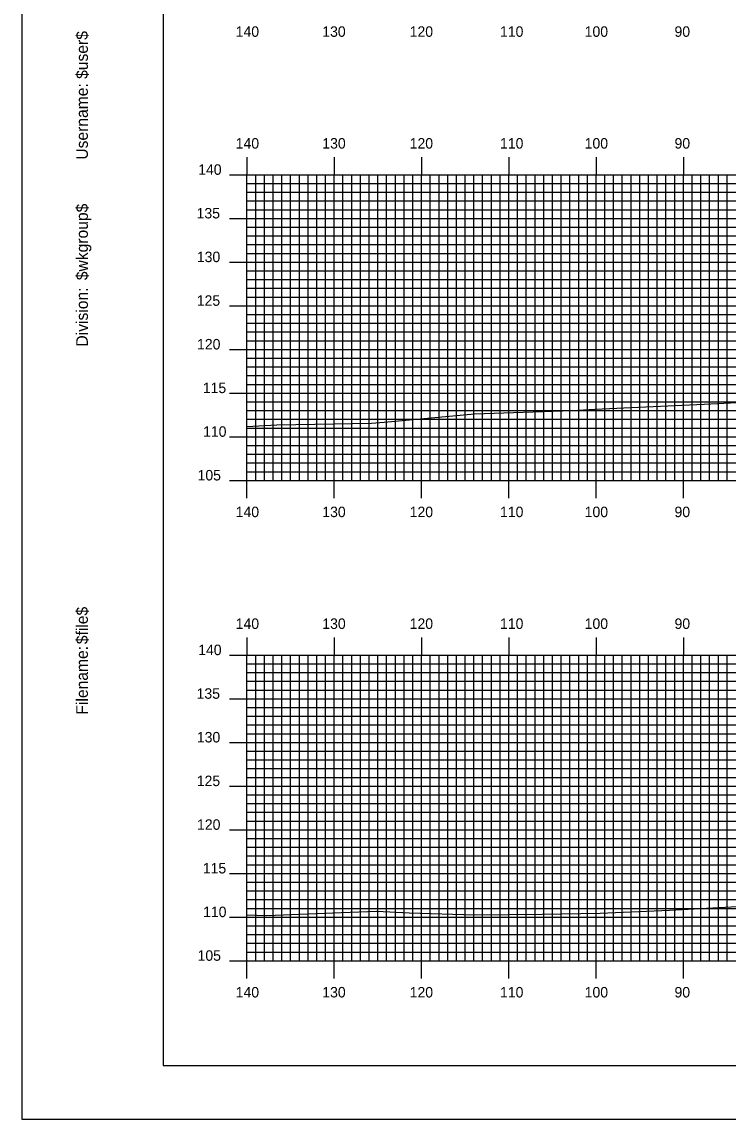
# Model space of a CAD drawing. Extents: x 1782254 to 1782597, y 442591 to 442811.
# Drawn here: x 1782253.6 to 1782334.5, y 442590.5 to 442716.2 of the extents above; entities that cross this region are included whole.
import ezdxf

# ---------------------------------------------------------------- set-up
doc = ezdxf.new("R2010")
doc.units = 0
for name, color, linetype in [('BORDER', 7, 'Continuous'), ('H_V ANNOTATION', 7, 'Continuous'), ('MAJOR', 7, 'Continuous'), ('MINOR', 7, 'Continuous'), ('PLOT BOUNDARY', 7, 'Continuous'), ('S_Roadway_Centerline', 7, 'Continuous')]:
    doc.layers.add(name, color=color, linetype=linetype)

msp = doc.modelspace()

# ---------------------------------------------------------------- linework, layer by layer
at = {"layer": 'BORDER'}
msp.add_lwpolyline([(1782269.83, 442596.67), (1782589.83, 442596.67), (1782589.83, 442806.67), (1782269.83, 442806.67)], close=True, dxfattribs=at)
at = {"layer": 'MAJOR'}
for p, q in [((1782279.43, 442700.67), (1782279.43, 442698.67)), ((1782289.43, 442700.67), (1782289.43, 442698.67)), ((1782299.43, 442700.67), (1782299.43, 442698.67)), ((1782309.43, 442700.67), (1782309.43, 442698.67)), ((1782319.43, 442700.67), (1782319.43, 442698.67)), ((1782329.43, 442700.67), (1782329.43, 442698.67)), ((1782277.43, 442698.67), (1782279.43, 442698.67)), ((1782279.43, 442698.67), (1782559.43, 442698.67)), ((1782279.43, 442663.67), (1782279.43, 442698.67)), ((1782279.43, 442663.67), (1782279.43, 442698.67)), ((1782279.43, 442698.67), (1782559.43, 442698.67)), ((1782289.43, 442663.67), (1782289.43, 442698.67)), ((1782299.43, 442663.67), (1782299.43, 442698.67)), ((1782309.43, 442663.67), (1782309.43, 442698.67)), ((1782319.43, 442663.67), (1782319.43, 442698.67)), ((1782329.43, 442663.67), (1782329.43, 442698.67)), ((1782277.43, 442693.67), (1782279.43, 442693.67)), ((1782279.43, 442693.67), (1782559.43, 442693.67)), ((1782277.43, 442688.67), (1782279.43, 442688.67)), ((1782279.43, 442688.67), (1782559.43, 442688.67)), ((1782277.43, 442683.67), (1782279.43, 442683.67)), ((1782279.43, 442683.67), (1782559.43, 442683.67)), ((1782277.43, 442678.67), (1782279.43, 442678.67)), ((1782279.43, 442678.67), (1782559.43, 442678.67)), ((1782277.43, 442673.67), (1782279.43, 442673.67)), ((1782279.43, 442673.67), (1782559.43, 442673.67)), ((1782277.43, 442668.67), (1782279.43, 442668.67)), ((1782279.43, 442668.67), (1782559.43, 442668.67)), ((1782277.43, 442663.67), (1782279.43, 442663.67)), ((1782279.43, 442663.67), (1782559.43, 442663.67)), ((1782279.43, 442663.67), (1782559.43, 442663.67)), ((1782279.43, 442661.66), (1782279.43, 442663.67)), ((1782289.43, 442661.66), (1782289.43, 442663.67)), ((1782299.43, 442661.66), (1782299.43, 442663.67)), ((1782309.43, 442661.66), (1782309.43, 442663.67)), ((1782319.43, 442661.66), (1782319.43, 442663.67)), ((1782329.43, 442661.66), (1782329.43, 442663.67)), ((1782279.43, 442645.67), (1782279.43, 442643.67)), ((1782289.43, 442645.67), (1782289.43, 442643.67)), ((1782299.43, 442645.67), (1782299.43, 442643.67)), ((1782309.43, 442645.67), (1782309.43, 442643.67)), ((1782319.43, 442645.67), (1782319.43, 442643.67)), ((1782329.43, 442645.67), (1782329.43, 442643.67)), ((1782277.43, 442643.67), (1782279.43, 442643.67)), ((1782279.43, 442643.67), (1782559.43, 442643.67)), ((1782279.43, 442608.67), (1782279.43, 442643.67)), ((1782279.43, 442608.67), (1782279.43, 442643.67)), ((1782279.43, 442643.67), (1782559.43, 442643.67)), ((1782289.43, 442608.67), (1782289.43, 442643.67)), ((1782299.43, 442608.67), (1782299.43, 442643.67)), ((1782309.43, 442608.67), (1782309.43, 442643.67)), ((1782319.43, 442608.67), (1782319.43, 442643.67)), ((1782329.43, 442608.67), (1782329.43, 442643.67)), ((1782277.43, 442638.67), (1782279.43, 442638.67)), ((1782279.43, 442638.67), (1782559.43, 442638.67)), ((1782277.43, 442633.67), (1782279.43, 442633.67)), ((1782279.43, 442633.67), (1782559.43, 442633.67)), ((1782277.43, 442628.67), (1782279.43, 442628.67)), ((1782279.43, 442628.67), (1782559.43, 442628.67)), ((1782277.43, 442623.67), (1782279.43, 442623.67)), ((1782279.43, 442623.67), (1782559.43, 442623.67)), ((1782277.43, 442618.67), (1782279.43, 442618.67)), ((1782279.43, 442618.67), (1782559.43, 442618.67)), ((1782277.43, 442613.67), (1782279.43, 442613.67)), ((1782279.43, 442613.67), (1782559.43, 442613.67)), ((1782277.43, 442608.67), (1782279.43, 442608.67)), ((1782279.43, 442608.67), (1782559.43, 442608.67)), ((1782279.43, 442608.67), (1782559.43, 442608.67)), ((1782279.43, 442606.66), (1782279.43, 442608.67)), ((1782289.43, 442606.66), (1782289.43, 442608.67)), ((1782299.43, 442606.66), (1782299.43, 442608.67)), ((1782309.43, 442606.66), (1782309.43, 442608.67)), ((1782319.43, 442606.66), (1782319.43, 442608.67)), ((1782329.43, 442606.66), (1782329.43, 442608.67))]:
    msp.add_line(p, q, dxfattribs=at)
at = {"layer": 'MINOR'}
for p, q in [((1782280.43, 442663.67), (1782280.43, 442698.67)), ((1782281.43, 442663.67), (1782281.43, 442698.67)), ((1782282.43, 442663.67), (1782282.43, 442698.67)), ((1782283.43, 442663.67), (1782283.43, 442698.67)), ((1782284.43, 442663.67), (1782284.43, 442698.67)), ((1782285.43, 442663.67), (1782285.43, 442698.67)), ((1782286.43, 442663.67), (1782286.43, 442698.67)), ((1782287.43, 442663.67), (1782287.43, 442698.67)), ((1782288.43, 442663.67), (1782288.43, 442698.67)), ((1782290.43, 442663.67), (1782290.43, 442698.67)), ((1782291.43, 442663.67), (1782291.43, 442698.67)), ((1782292.43, 442663.67), (1782292.43, 442698.67)), ((1782293.43, 442663.67), (1782293.43, 442698.67)), ((1782294.43, 442663.67), (1782294.43, 442698.67)), ((1782295.43, 442663.67), (1782295.43, 442698.67)), ((1782296.43, 442663.67), (1782296.43, 442698.67)), ((1782297.43, 442663.67), (1782297.43, 442698.67)), ((1782298.43, 442663.67), (1782298.43, 442698.67)), ((1782300.43, 442663.67), (1782300.43, 442698.67)), ((1782301.43, 442663.67), (1782301.43, 442698.67)), ((1782302.43, 442663.67), (1782302.43, 442698.67)), ((1782303.43, 442663.67), (1782303.43, 442698.67)), ((1782304.43, 442663.67), (1782304.43, 442698.67)), ((1782305.43, 442663.67), (1782305.43, 442698.67)), ((1782306.43, 442663.67), (1782306.43, 442698.67)), ((1782307.43, 442663.67), (1782307.43, 442698.67)), ((1782308.43, 442663.67), (1782308.43, 442698.67)), ((1782310.43, 442663.67), (1782310.43, 442698.67)), ((1782311.43, 442663.67), (1782311.43, 442698.67)), ((1782312.43, 442663.67), (1782312.43, 442698.67)), ((1782313.43, 442663.67), (1782313.43, 442698.67)), ((1782314.43, 442663.67), (1782314.43, 442698.67)), ((1782315.43, 442663.67), (1782315.43, 442698.67)), ((1782316.43, 442663.67), (1782316.43, 442698.67)), ((1782317.43, 442663.67), (1782317.43, 442698.67)), ((1782318.43, 442663.67), (1782318.43, 442698.67)), ((1782320.43, 442663.67), (1782320.43, 442698.67)), ((1782321.43, 442663.67), (1782321.43, 442698.67)), ((1782322.43, 442663.67), (1782322.43, 442698.67)), ((1782323.43, 442663.67), (1782323.43, 442698.67)), ((1782324.43, 442663.67), (1782324.43, 442698.67)), ((1782325.43, 442663.67), (1782325.43, 442698.67)), ((1782326.43, 442663.67), (1782326.43, 442698.67)), ((1782327.43, 442663.67), (1782327.43, 442698.67)), ((1782328.43, 442663.67), (1782328.43, 442698.67)), ((1782330.43, 442663.67), (1782330.43, 442698.67)), ((1782331.43, 442663.67), (1782331.43, 442698.67)), ((1782332.43, 442663.67), (1782332.43, 442698.67)), ((1782333.43, 442663.67), (1782333.43, 442698.67)), ((1782334.43, 442663.67), (1782334.43, 442698.67)), ((1782279.43, 442697.67), (1782559.43, 442697.67)), ((1782279.43, 442697.67), (1782281.44, 442697.67)), ((1782279.43, 442696.67), (1782559.43, 442696.67)), ((1782279.43, 442696.67), (1782281.44, 442696.67)), ((1782279.43, 442695.67), (1782559.43, 442695.67)), ((1782279.43, 442695.67), (1782281.44, 442695.67)), ((1782279.43, 442694.67), (1782559.43, 442694.67)), ((1782279.43, 442694.67), (1782281.44, 442694.67)), ((1782279.43, 442692.67), (1782559.43, 442692.67)), ((1782279.43, 442692.67), (1782281.44, 442692.67)), ((1782279.43, 442691.67), (1782559.43, 442691.67)), ((1782279.43, 442691.67), (1782281.44, 442691.67)), ((1782279.43, 442690.67), (1782559.43, 442690.67)), ((1782279.43, 442690.67), (1782281.44, 442690.67)), ((1782279.43, 442689.67), (1782559.43, 442689.67)), ((1782279.43, 442689.67), (1782281.44, 442689.67)), ((1782279.43, 442687.67), (1782559.43, 442687.67)), ((1782279.43, 442687.67), (1782281.44, 442687.67)), ((1782279.43, 442686.67), (1782559.43, 442686.67)), ((1782279.43, 442686.67), (1782281.44, 442686.67)), ((1782279.43, 442685.67), (1782559.43, 442685.67)), ((1782279.43, 442685.67), (1782281.44, 442685.67)), ((1782279.43, 442684.67), (1782559.43, 442684.67)), ((1782279.43, 442684.67), (1782281.44, 442684.67)), ((1782279.43, 442682.67), (1782559.43, 442682.67)), ((1782279.43, 442682.67), (1782281.44, 442682.67)), ((1782279.43, 442681.67), (1782559.43, 442681.67)), ((1782279.43, 442681.67), (1782281.44, 442681.67)), ((1782279.43, 442680.67), (1782559.43, 442680.67)), ((1782279.43, 442680.67), (1782281.44, 442680.67)), ((1782279.43, 442679.67), (1782559.43, 442679.67)), ((1782279.43, 442679.67), (1782281.44, 442679.67)), ((1782279.43, 442677.67), (1782559.43, 442677.67)), ((1782279.43, 442677.67), (1782281.44, 442677.67)), ((1782279.43, 442676.67), (1782559.43, 442676.67)), ((1782279.43, 442676.67), (1782281.44, 442676.67)), ((1782279.43, 442675.67), (1782559.43, 442675.67)), ((1782279.43, 442675.67), (1782281.44, 442675.67)), ((1782279.43, 442674.67), (1782559.43, 442674.67)), ((1782279.43, 442674.67), (1782281.44, 442674.67)), ((1782279.43, 442672.67), (1782559.43, 442672.67)), ((1782279.43, 442672.67), (1782281.44, 442672.67)), ((1782279.43, 442671.67), (1782559.43, 442671.67)), ((1782279.43, 442671.67), (1782281.44, 442671.67)), ((1782279.43, 442670.67), (1782559.43, 442670.67)), ((1782279.43, 442670.67), (1782281.44, 442670.67)), ((1782279.43, 442669.67), (1782559.43, 442669.67)), ((1782279.43, 442669.67), (1782281.44, 442669.67)), ((1782279.43, 442667.67), (1782559.43, 442667.67)), ((1782279.43, 442667.67), (1782281.44, 442667.67)), ((1782279.43, 442666.67), (1782559.43, 442666.67)), ((1782279.43, 442666.67), (1782281.44, 442666.67)), ((1782279.43, 442665.67), (1782559.43, 442665.67)), ((1782279.43, 442665.67), (1782281.44, 442665.67)), ((1782279.43, 442664.67), (1782559.43, 442664.67)), ((1782279.43, 442664.67), (1782281.44, 442664.67)), ((1782280.43, 442608.67), (1782280.43, 442643.67)), ((1782281.43, 442608.67), (1782281.43, 442643.67)), ((1782282.43, 442608.67), (1782282.43, 442643.67)), ((1782283.43, 442608.67), (1782283.43, 442643.67)), ((1782284.43, 442608.67), (1782284.43, 442643.67)), ((1782285.43, 442608.67), (1782285.43, 442643.67)), ((1782286.43, 442608.67), (1782286.43, 442643.67)), ((1782287.43, 442608.67), (1782287.43, 442643.67)), ((1782288.43, 442608.67), (1782288.43, 442643.67)), ((1782290.43, 442608.67), (1782290.43, 442643.67)), ((1782291.43, 442608.67), (1782291.43, 442643.67)), ((1782292.43, 442608.67), (1782292.43, 442643.67)), ((1782293.43, 442608.67), (1782293.43, 442643.67)), ((1782294.43, 442608.67), (1782294.43, 442643.67)), ((1782295.43, 442608.67), (1782295.43, 442643.67)), ((1782296.43, 442608.67), (1782296.43, 442643.67)), ((1782297.43, 442608.67), (1782297.43, 442643.67)), ((1782298.43, 442608.67), (1782298.43, 442643.67)), ((1782300.43, 442608.67), (1782300.43, 442643.67)), ((1782301.43, 442608.67), (1782301.43, 442643.67)), ((1782302.43, 442608.67), (1782302.43, 442643.67)), ((1782303.43, 442608.67), (1782303.43, 442643.67)), ((1782304.43, 442608.67), (1782304.43, 442643.67)), ((1782305.43, 442608.67), (1782305.43, 442643.67)), ((1782306.43, 442608.67), (1782306.43, 442643.67)), ((1782307.43, 442608.67), (1782307.43, 442643.67)), ((1782308.43, 442608.67), (1782308.43, 442643.67)), ((1782310.43, 442608.67), (1782310.43, 442643.67)), ((1782311.43, 442608.67), (1782311.43, 442643.67)), ((1782312.43, 442608.67), (1782312.43, 442643.67)), ((1782313.43, 442608.67), (1782313.43, 442643.67)), ((1782314.43, 442608.67), (1782314.43, 442643.67)), ((1782315.43, 442608.67), (1782315.43, 442643.67)), ((1782316.43, 442608.67), (1782316.43, 442643.67)), ((1782317.43, 442608.67), (1782317.43, 442643.67)), ((1782318.43, 442608.67), (1782318.43, 442643.67)), ((1782320.43, 442608.67), (1782320.43, 442643.67)), ((1782321.43, 442608.67), (1782321.43, 442643.67)), ((1782322.43, 442608.67), (1782322.43, 442643.67)), ((1782323.43, 442608.67), (1782323.43, 442643.67)), ((1782324.43, 442608.67), (1782324.43, 442643.67)), ((1782325.43, 442608.67), (1782325.43, 442643.67)), ((1782326.43, 442608.67), (1782326.43, 442643.67)), ((1782327.43, 442608.67), (1782327.43, 442643.67)), ((1782328.43, 442608.67), (1782328.43, 442643.67)), ((1782330.43, 442608.67), (1782330.43, 442643.67)), ((1782331.43, 442608.67), (1782331.43, 442643.67)), ((1782332.43, 442608.67), (1782332.43, 442643.67)), ((1782333.43, 442608.67), (1782333.43, 442643.67)), ((1782334.43, 442608.67), (1782334.43, 442643.67)), ((1782279.43, 442642.67), (1782559.43, 442642.67)), ((1782279.43, 442642.67), (1782281.44, 442642.67)), ((1782279.43, 442641.67), (1782559.43, 442641.67)), ((1782279.43, 442641.67), (1782281.44, 442641.67)), ((1782279.43, 442640.67), (1782559.43, 442640.67)), ((1782279.43, 442640.67), (1782281.44, 442640.67)), ((1782279.43, 442639.67), (1782559.43, 442639.67)), ((1782279.43, 442639.67), (1782281.44, 442639.67)), ((1782279.43, 442637.67), (1782559.43, 442637.67)), ((1782279.43, 442637.67), (1782281.44, 442637.67)), ((1782279.43, 442636.67), (1782559.43, 442636.67)), ((1782279.43, 442636.67), (1782281.44, 442636.67)), ((1782279.43, 442635.67), (1782559.43, 442635.67)), ((1782279.43, 442635.67), (1782281.44, 442635.67)), ((1782279.43, 442634.67), (1782559.43, 442634.67)), ((1782279.43, 442634.67), (1782281.44, 442634.67)), ((1782279.43, 442632.67), (1782559.43, 442632.67)), ((1782279.43, 442632.67), (1782281.44, 442632.67)), ((1782279.43, 442631.67), (1782559.43, 442631.67)), ((1782279.43, 442631.67), (1782281.44, 442631.67)), ((1782279.43, 442630.67), (1782559.43, 442630.67)), ((1782279.43, 442630.67), (1782281.44, 442630.67)), ((1782279.43, 442629.67), (1782559.43, 442629.67)), ((1782279.43, 442629.67), (1782281.44, 442629.67)), ((1782279.43, 442627.67), (1782559.43, 442627.67)), ((1782279.43, 442627.67), (1782281.44, 442627.67)), ((1782279.43, 442626.67), (1782559.43, 442626.67)), ((1782279.43, 442626.67), (1782281.44, 442626.67)), ((1782279.43, 442625.67), (1782559.43, 442625.67)), ((1782279.43, 442625.67), (1782281.44, 442625.67)), ((1782279.43, 442624.67), (1782559.43, 442624.67)), ((1782279.43, 442624.67), (1782281.44, 442624.67)), ((1782279.43, 442622.67), (1782559.43, 442622.67)), ((1782279.43, 442622.67), (1782281.44, 442622.67)), ((1782279.43, 442621.67), (1782559.43, 442621.67)), ((1782279.43, 442621.67), (1782281.44, 442621.67)), ((1782279.43, 442620.67), (1782559.43, 442620.67)), ((1782279.43, 442620.67), (1782281.44, 442620.67)), ((1782279.43, 442619.67), (1782559.43, 442619.67)), ((1782279.43, 442619.67), (1782281.44, 442619.67)), ((1782279.43, 442617.67), (1782559.43, 442617.67)), ((1782279.43, 442617.67), (1782281.44, 442617.67)), ((1782279.43, 442616.67), (1782559.43, 442616.67)), ((1782279.43, 442616.67), (1782281.44, 442616.67)), ((1782279.43, 442615.67), (1782559.43, 442615.67)), ((1782279.43, 442615.67), (1782281.44, 442615.67)), ((1782279.43, 442614.67), (1782559.43, 442614.67)), ((1782279.43, 442614.67), (1782281.44, 442614.67)), ((1782279.43, 442612.67), (1782559.43, 442612.67)), ((1782279.43, 442612.67), (1782281.44, 442612.67)), ((1782279.43, 442611.67), (1782559.43, 442611.67)), ((1782279.43, 442611.67), (1782281.44, 442611.67)), ((1782279.43, 442610.67), (1782559.43, 442610.67)), ((1782279.43, 442610.67), (1782281.44, 442610.67)), ((1782279.43, 442609.67), (1782559.43, 442609.67)), ((1782279.43, 442609.67), (1782281.44, 442609.67))]:
    msp.add_line(p, q, dxfattribs=at)
at = {"layer": 'PLOT BOUNDARY'}
msp.add_lwpolyline([(1782253.65, 442590.55), (1782593.65, 442590.55), (1782593.65, 442810.55), (1782253.65, 442810.55)], close=True, dxfattribs=at)
at = {"layer": 'S_Roadway_Centerline'}
for points in [[(1782279.43, 442669.86), (1782282.84, 442670.04), (1782293.7, 442670.23), (1782295.13, 442670.36), (1782305.51, 442671.3), (1782316.67, 442671.69), (1782319.27, 442671.85), (1782331.82, 442672.41), (1782339.36, 442672.79)], [(1782279.43, 442613.92), (1782281.69, 442613.84), (1782290.23, 442614.19), (1782294.3, 442614.37), (1782298, 442614.17), (1782305.54, 442613.92), (1782313.24, 442613.99), (1782319.9, 442614.13), (1782327.84, 442614.47), (1782337.05, 442614.95)]]:
    msp.add_lwpolyline(points, dxfattribs=at)

# ---------------------------------------------------------------- texts
at = {"layer": 'BORDER'}
for s, p in [('$user$', (1782261.2, 442709.65)), ('$user$', (1782261.2, 442709.65)), ('Username:', (1782261.2, 442700.4)), ('Username:', (1782261.2, 442700.4)), ('$wkgroup$', (1782261.2, 442686.6)), ('$wkgroup$', (1782261.2, 442686.6)), ('Division:', (1782261.2, 442679)), ('Division:', (1782261.2, 442679)), ('$file$', (1782261.2, 442644.92)), ('$file$', (1782261.2, 442644.92)), ('Filename:', (1782261.2, 442636.86)), ('Filename:', (1782261.2, 442636.86))]:
    msp.add_text(s, height=1.339, rotation=90, dxfattribs=at).set_placement(p)
at = {"layer": 'H_V ANNOTATION'}
for s, p in [('140', (1782278.14, 442714.47)), ('130', (1782288.06, 442714.47)), ('120', (1782298.07, 442714.47)), ('110', (1782308.42, 442714.47)), ('100', (1782318.12, 442714.47)), ('90', (1782328.41, 442714.47)), ('140', (1782278.14, 442701.67)), ('130', (1782288.06, 442701.67)), ('120', (1782298.07, 442701.67)), ('110', (1782308.42, 442701.67)), ('100', (1782318.12, 442701.67)), ('90', (1782328.41, 442701.67)), ('140', (1782273.84, 442698.67)), ('135', (1782273.66, 442693.67)), ('130', (1782273.69, 442688.67)), ('125', (1782273.68, 442683.67)), ('120', (1782273.71, 442678.67)), ('115', (1782274.37, 442673.67)), ('110', (1782274.4, 442668.67)), ('105', (1782273.77, 442663.67)), ('140', (1782278.14, 442659.47)), ('130', (1782288.06, 442659.47)), ('120', (1782298.07, 442659.47)), ('110', (1782308.42, 442659.47)), ('100', (1782318.12, 442659.47)), ('90', (1782328.41, 442659.47)), ('140', (1782278.14, 442646.67)), ('130', (1782288.06, 442646.67)), ('120', (1782298.07, 442646.67)), ('110', (1782308.42, 442646.67)), ('100', (1782318.12, 442646.67)), ('90', (1782328.41, 442646.67)), ('140', (1782273.84, 442643.67)), ('135', (1782273.66, 442638.67)), ('130', (1782273.69, 442633.67)), ('125', (1782273.68, 442628.67)), ('120', (1782273.71, 442623.67)), ('115', (1782274.37, 442618.67)), ('110', (1782274.4, 442613.67)), ('105', (1782273.77, 442608.67)), ('140', (1782278.14, 442604.47)), ('130', (1782288.06, 442604.47)), ('120', (1782298.07, 442604.47)), ('110', (1782308.42, 442604.47)), ('100', (1782318.12, 442604.47)), ('90', (1782328.41, 442604.47))]:
    msp.add_text(s, height=1.2, dxfattribs=at).set_placement(p)
at = {"layer": 'MAJOR'}
for p in [(1782279.42, 442663.67), (1782279.42, 442608.67)]:
    msp.add_text('-', height=0.012, dxfattribs=at).set_placement(p)

doc.saveas('drawing.dxf')
